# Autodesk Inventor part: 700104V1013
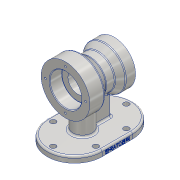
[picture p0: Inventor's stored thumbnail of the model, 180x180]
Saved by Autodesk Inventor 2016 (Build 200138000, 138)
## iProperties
Created: 2020-01
Part Number: 700104V1013
Material: 알루미늄 6061
Document SubType Name: Modeling
Designer: woori
Density: 2.7 g/cm^3
Appearance: 알루미늄 - 평지
Mass: 938.148 g
Surface Area: 654.119 cm^2
Volume: 347.462 cm^3
Author: woori
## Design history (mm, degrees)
sketch "스케치1"
  geometry: L1 (-25, 0)-(25, 0); L2 (-25, -45)-(25, -45); L3 (25, 45)-(-25, 45); A1 r 45 centre (-25, 0) between (-25, 45) and (-25, -45); A2 r 45 centre (25, 0) between (25, -45) and (25, 45); 2 further points
  constraints: 8 end point, 4 point on circle, 4 tangent, 2 centre point, 1 coincident, 1 horizontal, 1 midpoint, 1 parallel
  dimensions: "d0" = 50 distance of L3.start L3.end; "d1" = 45 radius of A1
extrude "돌출1" new body sketch "스케치1" distance "d2" = 10; taper "d3" = 0 deg
sketch "스케치2"
  geometry: L1 (0, 80)-(0, 0); L2 (0, 80)-(40, 80); L3 (40, 80)-(40, 115); L4 (40, 115)-(24, 115); L5 (24, 115)-(13.289, 107.5); L6 (13.289, 107.5)-(-1.103, 107.5); L7 (-1.103, 107.5)-(-16, 120); L8 (-16, 120)-(-40, 120); L9 (-40, 120)-(-40, 80); L10 (-40, 80)-(0, 80); L11 (-25, 0)-(-70, 0) reference; L12 (-70, 0)-(-70, 19.736)
  constraints: 22 end point, 4 perpendicular, 2 parallel, 2 vertical, 1 horizontal, 1 point on line
  dimensions: "d4" = 80 distance of L1.start L1.end; "d5" = 35 deg angle of L6 L5; "d6" = 40 deg angle of L6 L7; "d7" = 16 distance of L3.end L4.end; "d8" = 24 distance of L7.end L8.end; "d9" = 80 distance between parallel lines of L3 L9; "d10" = 55 diameter of L6 L10; "d11" = 80 diameter of L8 L10; "d12" = 70 diameter of L4 L2; "d13" = 30 distance between parallel lines of L12 L9
sketch "스케치3"
  geometry: L1 (-25, -45)-(25, -45) reference; L2 (25, 45)-(-25, 45) reference; L3 (0, 0)-(70, 0); A1 r 45 centre (25, 0) between (25, -45) and (25, 45) reference; A2 r 45 centre (-25, 0) between (-25, 45) and (-25, -45) reference
  constraints: 2 end point, 1 point on circle
revolve "회전1" stored, may be unused: angle "d14" = 90 deg
sketch "스케치4"
  geometry: L1 (23.814, -5)-(-30, -5); L2 (-30, -5)-(-30, 5); L3 (-30, 5)-(23.814, 5); L4 (23.814, 5)-(23.814, -5); L5 (23.814, -5)-(-30, 5); L6 (-30, -5)-(23.814, 5); L7 (12, 0)-(70, 0); C1 r 16 at (12, 0); A1 r 45 centre (25, 0) between (25, -45) and (25, 45) reference; 4 further points
  constraints: 14 end point, 4 midpoint, 2 parallel, 1 centre point, 1 horizontal, 1 horizontal alignment, 1 perpendicular, 1 point on circle
  dimensions: "d15" = 58 distance of L7.end L7.start; "d16" = 10 distance between parallel lines of L3 L1; "d17" = 32 diameter of C1; "d18" = 100 distance from line of L7.end L2
extrude "돌출2" join sketch "스케치4" stored distance "d19" = 10; taper "d20" = 0 deg
sketch "스케치5"
  geometry: L1 (-24.855, 0)-(25.145, 0); L2 (-24.855, -35)-(25.145, -35); L3 (25.145, 35)-(-24.855, 35); A1 r 35 centre (-24.855, 0) between (-24.855, 35) and (-24.855, -35); A2 r 35 centre (25.145, 0) between (25.145, -35) and (25.145, 35); 8 further points
  constraints: 8 end point, 6 point on circle, 4 coincident, 4 tangent, 2 centre point, 1 horizontal, 1 midpoint, 1 parallel
  dimensions: "d21" = 50 distance of L3.start L3.end; "d22" = 35 radius of A1
hole "구멍1" sketch "스케치5" at (-24.855, 35), (25.145, 35), (25.145, -35), (-24.855, -35), (-59.855, 0), (60.145, 0) diameter "d23" = 9; stored, may be unused: countersink angle "d27" = 90 deg, drill point angle "d29" = 0 deg; dims "d24" = 6, "d25" = 4, "d26" = 2, "d28" = 6
fillet "모깎기1" dims "d30" = 3
fillet "모깎기2" dims "d31" = 3
fillet "모깎기3" dims "d32" = 3
sketch "스케치6"
  geometry: L1 (-40, 40)-(-40, 120) reference; L2 (-40, 80)-(-20, 80); L3 (-20, 80)-(-20, 106); L4 (-20, 106)-(-40, 106); L5 (-40, 106)-(-40, 80); L6 (-20, 80)-(23, 80); L7 (23, 80)-(23, 96); L8 (23, 96)-(-20, 96); L9 (-20, 96)-(-20, 80); L10 (40, 45)-(40, 115) reference; L11 (23, 80)-(40, 80); L12 (40, 80)-(40, 100); L13 (40, 100)-(23, 100); L14 (23, 100)-(23, 80); 1 further point
  constraints: 24 end point, 6 parallel, 3 horizontal, 3 perpendicular, 1 midpoint, 1 point on line
  dimensions: "d33" = 52 diameter of L4 L2; "d34" = 32 diameter of L8 L6; "d35" = 40 diameter of L13 L11; "d36" = 20 distance between parallel lines of L1 L3; "d37" = 17 distance between parallel lines of L10 L7
revolve "회전2" sketch "스케치6" stored, may be unused: angle "d38" = 90 deg
fillet "모깎기4" dims "d39" = 0.3
chamfer "모따기1" distance "d40" = 1; stored, may be unused: second distance "d41" = 2, angle "d42" = 45 deg
fillet "모깎기5" dims "d43" = 3
sketch "스케치7" dims "d44" = 66
  geometry: C1 r 27 at (0, 0) reference; 3 further points
  constraints: 1 coincident, 1 horizontal alignment, 2 other
hole "구멍2" sketch "스케치7" at (-33, 0) diameter "d45" = 3.242; stored, may be unused: countersink angle "d49" = 90 deg, drill point angle "d51" = 118 deg; dims "d46" = 9, "d47" = 4, "d48" = 2, "d50" = 11
sketch "스케치8" dims "d55" = 55
  geometry: C1 r 21 at (0, 0) reference; 3 further points
  constraints: 1 coincident, 1 horizontal alignment, 2 other
hole "구멍3" sketch "스케치8" at (27.5, 0) diameter "d56" = 3.242; stored, may be unused: countersink angle "d60" = 90 deg, drill point angle "d62" = 118 deg; dims "d57" = 9, "d58" = 4, "d59" = 2, "d61" = 11
sketch "스케치9"
  geometry: L1 (50, 0)-(0, 0) reference; L2 (25, -4)-(95, -3.5); L3 (95, 0)-(95, -7) reference; 1 further point
  constraints: 2 end point, 1 midpoint, 1 other
  dimensions: "d66" = 70 distance from line of L3 L2.start; "d67" = 4 distance from line of L1 L2.start
feature "엠보싱1" sketch "스케치9" dims "d68" = 0.5, "d69" = 0
fillet "모깎기6" dims "d70" = 3
node "솔리드1"
pattern_circular "원형 패턴1" dims angle "d53" = 360 deg
pattern_circular "원형 패턴2" dims angle "d64" = 360 deg
